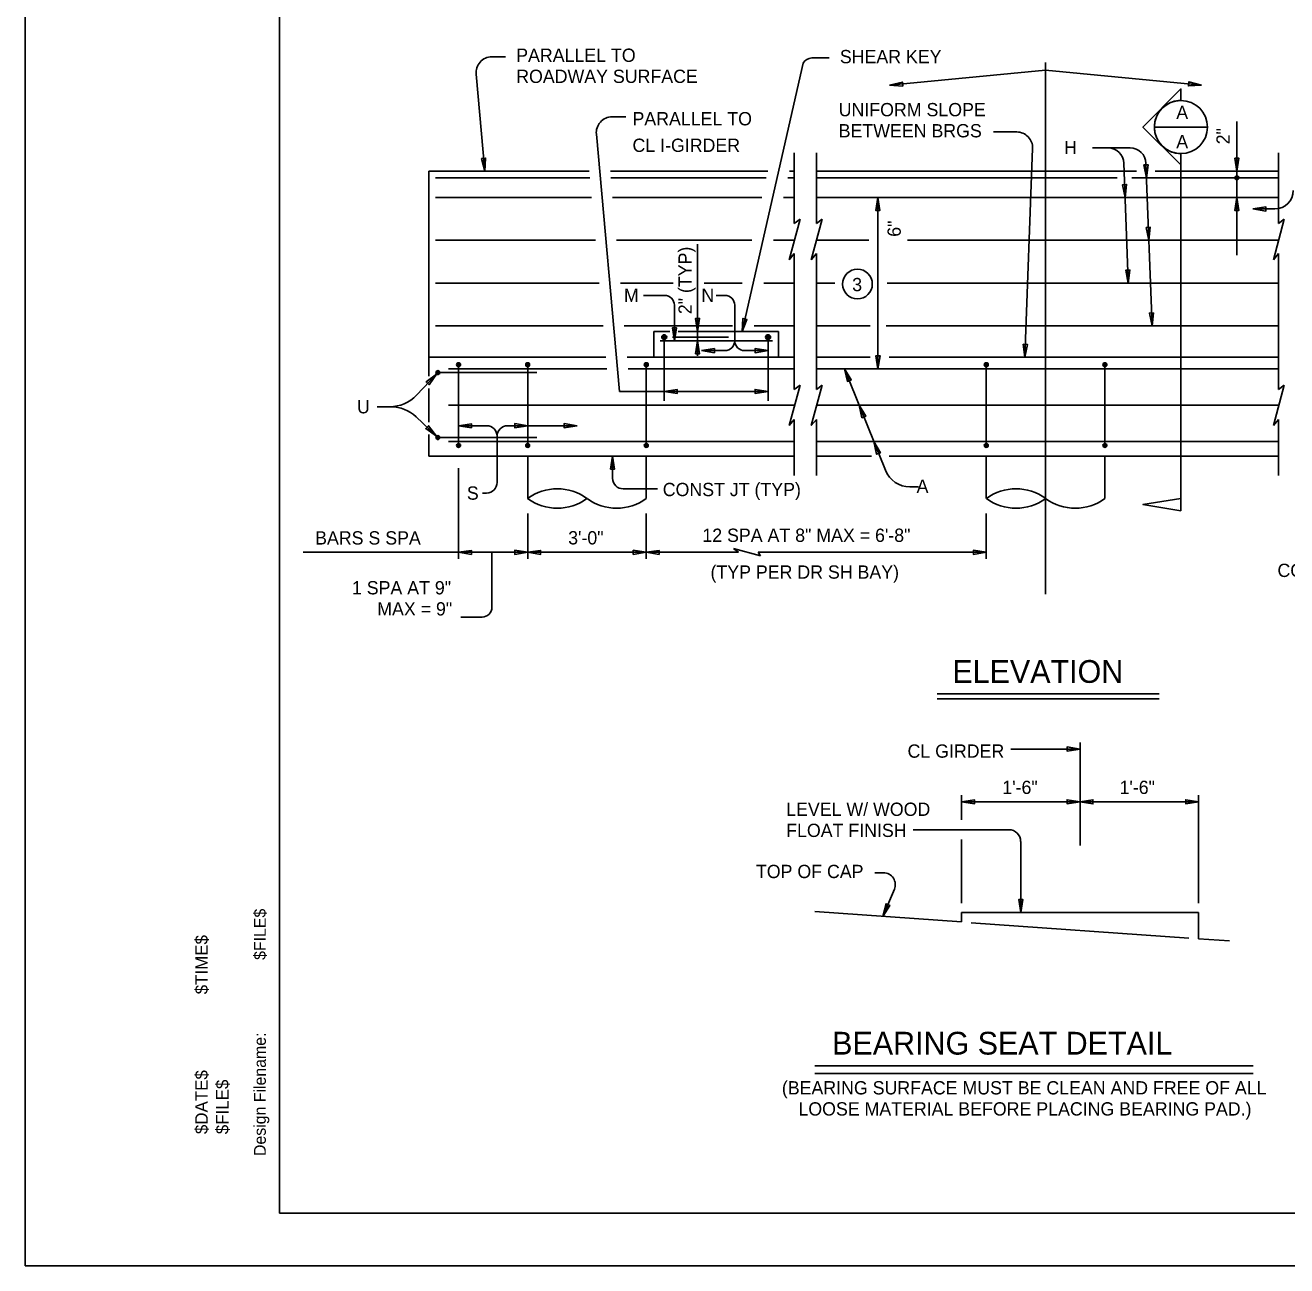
# Model space of a CAD drawing. Extents: x 926 to 1074, y 990 to 1081.
# Drawn here: x 1000 to 1011.97, y 1000 to 1011.77 of the extents above; entities that cross this region are included whole.
import ezdxf

# ---------------------------------------------------------------- set-up
doc = ezdxf.new("R2010")
doc.units = 0
for name, color, linetype in [('BORD_lines_major', 7, 'Continuous'), ('BORD_text_filename_date', 7, 'Continuous'), ('D_BATCH_PLOT', 7, 'Continuous'), ('D_SHEET', 7, 'Continuous'), ('D_SHEET_TXT_SUB_CODE', 7, 'Continuous'), ('Default', 7, 'Continuous'), ('Working Level 1', 7, 'Continuous')]:
    doc.layers.add(name, color=color, linetype=linetype)

msp = doc.modelspace()

# ---------------------------------------------------------------- linework, layer by layer
at = {"layer": 'BORD_lines_major'}
for q in [(1002.413, 1021.382), (1033.5, 1000.5)]:
    msp.add_line((1002.413, 1000.5), q, dxfattribs=at)
at = {"layer": 'D_BATCH_PLOT'}
msp.add_lwpolyline([(1000, 1000), (1034, 1000), (1034, 1022), (1000, 1022)], close=True, dxfattribs=at)
at = {"layer": 'D_SHEET'}
for q in [(1000, 1022), (1034, 1000)]:
    msp.add_line((1000, 1000), q, dxfattribs=at)
at = {"layer": 'Default'}
msp.add_line((1010.71, 1010.801), (1011.214, 1010.801), dxfattribs=at)
for points in [[(1010.962, 1011.053), (1010.94, 1011.052), (1010.919, 1011.049), (1010.897, 1011.045), (1010.876, 1011.038), (1010.856, 1011.03), (1010.836, 1011.019), (1010.818, 1011.008), (1010.8, 1010.994), (1010.784, 1010.979), (1010.769, 1010.963), (1010.756, 1010.946), (1010.744, 1010.927), (1010.734, 1010.908), (1010.726, 1010.887), (1010.719, 1010.866), (1010.714, 1010.845), (1010.711, 1010.823), (1010.71, 1010.801), (1010.711, 1010.779), (1010.714, 1010.757), (1010.719, 1010.736), (1010.726, 1010.715), (1010.734, 1010.695), (1010.744, 1010.675), (1010.756, 1010.657), (1010.769, 1010.639), (1010.784, 1010.623), (1010.8, 1010.608), (1010.818, 1010.595), (1010.836, 1010.583), (1010.856, 1010.573), (1010.876, 1010.564), (1010.897, 1010.558), (1010.919, 1010.553), (1010.94, 1010.55), (1010.962, 1010.549), (1010.962, 1010.441), (1010.602, 1010.801), (1010.962, 1011.162)], [(1010.962, 1007.162), (1010.602, 1007.22), (1010.962, 1007.278)]]:
    msp.add_lwpolyline(points, close=True, dxfattribs=at)
msp.add_lwpolyline([(1010.962, 1010.549), (1010.962, 1007.162)], dxfattribs=at)
msp.add_circle((1010.962, 1010.801), 0.252, dxfattribs=at)
at = {"layer": 'Working Level 1'}
for p, q in [((1004.426, 1011.467), (1004.555, 1011.467)), ((1006.799, 1008.862), (1007.379, 1011.407)), ((1007.627, 1011.456), (1007.461, 1011.456)), ((1009.679, 1006.37), (1009.679, 1011.412)), ((1004.36, 1010.383), (1004.277, 1011.301)), ((1009.679, 1011.339), (1008.199, 1011.198)), ((1009.679, 1011.339), (1011.158, 1011.198)), ((1005.567, 1010.898), (1005.696, 1010.898)), ((1011.493, 1009.585), (1011.493, 1010.852)), ((1005.638, 1008.293), (1005.418, 1010.732)), ((1009.405, 1010.754), (1009.184, 1010.754)), ((1007.294, 1009.887), (1007.294, 1010.555)), ((1007.504, 1009.887), (1007.504, 1010.555)), ((1009.481, 1008.617), (1009.555, 1010.598)), ((1010.125, 1010.603), (1010.481, 1010.603)), ((1011.888, 1009.887), (1011.888, 1010.555)), ((1010.463, 1009.342), (1010.421, 1010.459)), ((1010.688, 1008.915), (1010.63, 1010.459)), ((1003.828, 1010.383), (1003.828, 1008.617)), ((1005.349, 1010.383), (1003.828, 1010.383)), ((1005.354, 1010.32), (1003.891, 1010.32)), ((1007.043, 1010.383), (1005.55, 1010.383)), ((1007.029, 1010.32), (1005.555, 1010.32)), ((1007.294, 1010.32), (1007.234, 1010.32)), ((1007.294, 1010.383), (1007.248, 1010.383)), ((1010.541, 1010.383), (1007.504, 1010.383)), ((1010.358, 1010.32), (1007.504, 1010.32)), ((1011.888, 1010.32), (1010.497, 1010.32)), ((1011.888, 1010.383), (1010.719, 1010.383)), ((1005.371, 1010.133), (1003.891, 1010.133)), ((1006.986, 1010.133), (1005.572, 1010.133)), ((1007.294, 1010.133), (1007.191, 1010.133)), ((1011.888, 1010.133), (1007.504, 1010.133)), ((1008.088, 1008.509), (1008.088, 1010.133)), ((1011.645, 1010.024), (1011.853, 1010.024)), ((1007.246, 1009.542), (1007.35, 1009.926)), ((1007.35, 1009.926), (1007.294, 1009.887)), ((1007.455, 1009.542), (1007.559, 1009.926)), ((1007.559, 1009.926), (1007.504, 1009.887)), ((1011.839, 1009.542), (1011.943, 1009.926)), ((1011.943, 1009.926), (1011.888, 1009.887)), ((1005.408, 1009.727), (1003.891, 1009.727)), ((1006.893, 1009.727), (1005.609, 1009.727)), ((1007.296, 1009.727), (1007.099, 1009.727)), ((1008.003, 1009.727), (1007.505, 1009.727)), ((1008.37, 1009.727), (1011.889, 1009.727)), ((1006.377, 1008.631), (1006.377, 1009.691)), ((1007.294, 1009.601), (1007.246, 1009.542)), ((1007.294, 1008.313), (1007.294, 1009.601)), ((1007.504, 1009.601), (1007.455, 1009.542)), ((1007.504, 1008.313), (1007.504, 1009.601)), ((1011.888, 1009.601), (1011.839, 1009.542)), ((1011.888, 1008.313), (1011.888, 1009.601)), ((1005.445, 1009.321), (1003.891, 1009.321)), ((1006.145, 1009.321), (1005.645, 1009.321)), ((1006.801, 1009.321), (1006.44, 1009.321)), ((1007.294, 1009.321), (1007.006, 1009.321)), ((1007.68, 1009.321), (1007.504, 1009.321)), ((1008.176, 1009.321), (1011.888, 1009.321)), ((1006.064, 1009.203), (1005.865, 1009.203)), ((1006.158, 1008.772), (1006.158, 1009.11)), ((1006.554, 1009.203), (1006.636, 1009.203)), ((1006.73, 1008.774), (1006.73, 1009.11)), ((1005.481, 1008.915), (1003.891, 1008.915)), ((1006.708, 1008.915), (1005.682, 1008.915)), ((1007.294, 1008.915), (1006.914, 1008.915)), ((1008.015, 1008.915), (1007.504, 1008.915)), ((1008.167, 1008.915), (1011.888, 1008.915)), ((1005.961, 1008.862), (1006.115, 1008.862)), ((1005.961, 1008.617), (1005.961, 1008.862)), ((1007.088, 1008.772), (1006.023, 1008.772)), ((1006.061, 1008.205), (1006.061, 1008.808)), ((1006.67, 1008.808), (1006.139, 1008.808)), ((1006.193, 1008.862), (1007.146, 1008.862)), ((1007.046, 1008.205), (1007.046, 1008.808)), ((1007.146, 1008.862), (1007.146, 1008.617)), ((1006.636, 1008.68), (1006.414, 1008.68)), ((1007.046, 1008.68), (1006.824, 1008.68)), ((1003.828, 1008.617), (1003.828, 1008.438)), ((1005.508, 1008.617), (1003.828, 1008.617)), ((1005.518, 1008.509), (1004.016, 1008.509)), ((1004.11, 1008.547), (1004.11, 1007.781)), ((1004.766, 1008.547), (1004.766, 1007.781)), ((1007.294, 1008.617), (1005.709, 1008.617)), ((1007.294, 1008.509), (1005.719, 1008.509)), ((1005.891, 1008.547), (1005.891, 1007.781)), ((1008.015, 1008.617), (1007.504, 1008.617)), ((1011.888, 1008.509), (1007.504, 1008.509)), ((1008.159, 1007.545), (1007.772, 1008.509)), ((1008.194, 1008.617), (1009.679, 1008.617)), ((1009.116, 1008.547), (1009.116, 1007.781)), ((1009.669, 1008.617), (1011.888, 1008.617)), ((1010.241, 1008.547), (1010.241, 1007.781)), ((1003.901, 1008.458), (1003.711, 1008.257)), ((1004.852, 1008.472), (1003.914, 1008.472)), ((1003.828, 1008.321), (1003.828, 1008.001)), ((1007.046, 1008.293), (1005.638, 1008.293)), ((1007.246, 1007.969), (1007.35, 1008.353)), ((1007.35, 1008.353), (1007.294, 1008.313)), ((1007.455, 1007.969), (1007.559, 1008.353)), ((1007.559, 1008.353), (1007.504, 1008.313)), ((1011.839, 1007.969), (1011.943, 1008.353)), ((1011.943, 1008.353), (1011.888, 1008.313)), ((1007.299, 1008.164), (1004.016, 1008.164)), ((1011.892, 1008.164), (1007.508, 1008.164)), ((1003.339, 1008.148), (1003.467, 1008.148)), ((1003.708, 1008.052), (1003.901, 1007.869)), ((1004.11, 1007.968), (1004.379, 1007.968)), ((1004.576, 1007.968), (1005.235, 1007.968)), ((1007.294, 1008.027), (1007.246, 1007.969)), ((1007.294, 1007.495), (1007.294, 1008.027)), ((1007.504, 1008.027), (1007.455, 1007.969)), ((1007.504, 1007.495), (1007.504, 1008.027)), ((1011.888, 1008.027), (1011.839, 1007.969)), ((1011.888, 1007.495), (1011.888, 1008.027)), ((1003.828, 1007.885), (1003.828, 1007.679)), ((1004.852, 1007.856), (1003.914, 1007.856)), ((1007.294, 1007.818), (1004.016, 1007.818)), ((1004.476, 1007.868), (1004.476, 1007.429)), ((1011.888, 1007.818), (1007.504, 1007.818)), ((1007.294, 1007.679), (1003.828, 1007.679)), ((1004.766, 1007.679), (1004.766, 1007.278)), ((1005.572, 1007.679), (1005.572, 1007.469)), ((1005.891, 1007.679), (1005.891, 1007.278)), ((1008.028, 1007.679), (1007.504, 1007.679)), ((1011.888, 1007.679), (1008.194, 1007.679)), ((1009.116, 1007.679), (1009.116, 1007.278)), ((1009.116, 1007.679), (1009.116, 1007.278)), ((1009.116, 1007.679), (1009.116, 1007.278)), ((1009.116, 1007.679), (1009.116, 1007.278)), ((1009.116, 1007.679), (1009.116, 1007.278)), ((1009.116, 1007.679), (1009.116, 1007.278)), ((1010.241, 1007.679), (1010.241, 1007.278)), ((1004.11, 1007.564), (1004.11, 1006.706)), ((1004.376, 1007.329), (1004.338, 1007.329)), ((1005.672, 1007.369), (1005.998, 1007.369)), ((1008.473, 1007.388), (1008.391, 1007.388)), ((1004.766, 1007.136), (1004.766, 1006.706)), ((1005.891, 1007.136), (1005.891, 1006.706)), ((1009.116, 1007.136), (1009.116, 1006.706)), ((1006.765, 1006.767), (1002.635, 1006.767)), ((1004.427, 1006.767), (1004.427, 1006.247)), ((1006.765, 1006.767), (1006.719, 1006.804)), ((1006.719, 1006.804), (1006.975, 1006.735)), ((1006.975, 1006.735), (1006.953, 1006.767)), ((1009.116, 1006.767), (1006.953, 1006.767)), ((1004.333, 1006.153), (1004.133, 1006.153)), ((1008.65, 1005.426), (1010.756, 1005.426)), ((1008.65, 1005.376), (1010.756, 1005.376)), ((1010.005, 1004.963), (1010.005, 1004.838)), ((1010.005, 1004.901), (1009.349, 1004.901)), ((1010.005, 1003.986), (1010.005, 1004.838)), ((1008.88, 1004.23), (1008.88, 1004.463)), ((1011.13, 1003.438), (1011.13, 1004.463)), ((1008.88, 1004.401), (1011.13, 1004.401)), ((1008.423, 1004.136), (1009.33, 1004.136)), ((1008.88, 1003.438), (1008.88, 1004.042)), ((1009.443, 1003.351), (1009.443, 1004.024)), ((1008.06, 1003.728), (1008.141, 1003.728)), ((1008.244, 1003.571), (1008.135, 1003.313)), ((1008.88, 1003.261), (1007.49, 1003.359)), ((1008.88, 1003.351), (1011.13, 1003.351)), ((1008.88, 1003.261), (1008.88, 1003.351)), ((1008.974, 1003.254), (1011.037, 1003.107)), ((1011.13, 1003.351), (1011.13, 1003.102)), ((1011.423, 1003.082), (1011.13, 1003.102)), ((1007.489, 1001.895), (1011.649, 1001.895)), ((1007.489, 1001.825), (1011.649, 1001.825))]:
    msp.add_line(p, q, dxfattribs=at)
for points in [[(1008.199, 1011.198), (1008.323, 1011.19), (1008.32, 1011.228)], [(1011.158, 1011.198), (1011.038, 1011.23), (1011.034, 1011.191)], [(1004.36, 1010.383), (1004.367, 1010.506), (1004.328, 1010.502)], [(1010.636, 1010.32), (1010.611, 1010.442), (1010.65, 1010.443)], [(1011.493, 1010.383), (1011.513, 1010.505), (1011.475, 1010.505)], [(1010.433, 1010.133), (1010.409, 1010.254), (1010.447, 1010.256)], [(1008.088, 1010.133), (1008.068, 1010.01), (1008.107, 1010.01)], [(1011.493, 1010.133), (1011.473, 1010.01), (1011.512, 1010.01)], [(1011.645, 1010.024), (1011.768, 1010.004), (1011.768, 1010.043)], [(1010.658, 1009.727), (1010.633, 1009.848), (1010.672, 1009.85)], [(1010.463, 1009.321), (1010.439, 1009.443), (1010.478, 1009.444)], [(1010.688, 1008.915), (1010.664, 1009.037), (1010.702, 1009.038)], [(1006.158, 1008.772), (1006.178, 1008.895), (1006.139, 1008.895)], [(1006.377, 1008.862), (1006.397, 1008.985), (1006.358, 1008.985)], [(1006.799, 1008.862), (1006.807, 1008.986), (1006.845, 1008.977)], [(1006.377, 1008.772), (1006.397, 1008.65), (1006.358, 1008.65)], [(1006.414, 1008.68), (1006.537, 1008.66), (1006.537, 1008.699)], [(1007.046, 1008.68), (1006.923, 1008.66), (1006.923, 1008.699)], [(1008.088, 1008.509), (1008.108, 1008.632), (1008.069, 1008.632)], [(1009.481, 1008.617), (1009.506, 1008.739), (1009.467, 1008.74)], [(1007.772, 1008.509), (1007.799, 1008.388), (1007.835, 1008.402)], [(1003.901, 1008.458), (1003.803, 1008.383), (1003.831, 1008.356)], [(1006.061, 1008.293), (1006.183, 1008.273), (1006.183, 1008.312)], [(1007.046, 1008.293), (1006.923, 1008.313), (1006.923, 1008.274)], [(1007.91, 1008.164), (1007.937, 1008.043), (1007.973, 1008.057)], [(1003.901, 1007.869), (1003.826, 1007.968), (1003.799, 1007.94)], [(1004.11, 1007.968), (1004.232, 1007.948), (1004.232, 1007.986)], [(1004.766, 1007.968), (1004.643, 1007.988), (1004.643, 1007.949)], [(1005.235, 1007.968), (1005.112, 1007.988), (1005.112, 1007.949)], [(1008.049, 1007.818), (1008.076, 1007.697), (1008.112, 1007.712)], [(1005.572, 1007.679), (1005.552, 1007.557), (1005.59, 1007.557)], [(1004.11, 1006.767), (1004.232, 1006.747), (1004.232, 1006.785)], [(1004.766, 1006.767), (1004.643, 1006.787), (1004.643, 1006.748)], [(1004.766, 1006.767), (1004.888, 1006.747), (1004.888, 1006.785)], [(1005.891, 1006.767), (1005.768, 1006.787), (1005.768, 1006.748)], [(1005.891, 1006.767), (1006.013, 1006.747), (1006.013, 1006.785)], [(1009.116, 1006.767), (1008.994, 1006.787), (1008.994, 1006.748)], [(1010.005, 1004.901), (1009.883, 1004.921), (1009.883, 1004.882)], [(1008.88, 1004.401), (1009.003, 1004.381), (1009.003, 1004.42)], [(1010.005, 1004.401), (1009.883, 1004.421), (1009.883, 1004.382)], [(1010.005, 1004.401), (1010.128, 1004.381), (1010.128, 1004.42)], [(1011.13, 1004.401), (1011.008, 1004.421), (1011.008, 1004.382)], [(1008.135, 1003.313), (1008.201, 1003.418), (1008.166, 1003.433)], [(1009.443, 1003.351), (1009.463, 1003.473), (1009.424, 1003.473)]]:
    msp.add_lwpolyline(points, close=True, dxfattribs=at)
for centre, radius in [((1011.493, 1010.32), 0.0187), ((1011.493, 1010.32), 0.0117), ((1011.493, 1010.32), 0.00469), ((1007.894, 1009.312), 0.141), ((1006.061, 1008.808), 0.0235), ((1006.061, 1008.808), 0.0188), ((1006.061, 1008.808), 0.0141), ((1006.061, 1008.808), 0.0094), ((1006.061, 1008.808), 0.0047), ((1007.046, 1008.808), 0.0235), ((1007.046, 1008.808), 0.0188), ((1007.046, 1008.808), 0.0141), ((1007.046, 1008.808), 0.0094), ((1007.046, 1008.808), 0.0047), ((1004.11, 1008.547), 0.0187), ((1004.11, 1008.547), 0.0117), ((1004.11, 1008.547), 0.00469), ((1004.766, 1008.547), 0.0187), ((1004.766, 1008.547), 0.0117), ((1004.766, 1008.547), 0.00469), ((1005.891, 1008.547), 0.0187), ((1005.891, 1008.547), 0.0117), ((1005.891, 1008.547), 0.00469), ((1009.116, 1008.547), 0.0187), ((1009.116, 1008.547), 0.0117), ((1009.116, 1008.547), 0.00469), ((1010.241, 1008.547), 0.0187), ((1010.241, 1008.547), 0.0117), ((1010.241, 1008.547), 0.00469), ((1003.914, 1008.472), 0.0187), ((1003.914, 1008.472), 0.0117), ((1003.914, 1008.472), 0.00469), ((1003.914, 1007.856), 0.0187), ((1003.914, 1007.856), 0.0117), ((1003.914, 1007.856), 0.00469), ((1004.11, 1007.781), 0.0187), ((1004.11, 1007.781), 0.0117), ((1004.766, 1007.781), 0.0187), ((1004.766, 1007.781), 0.0117), ((1005.891, 1007.781), 0.0187), ((1005.891, 1007.781), 0.0117), ((1009.116, 1007.781), 0.0187), ((1009.116, 1007.781), 0.0117), ((1010.241, 1007.781), 0.0187), ((1010.241, 1007.781), 0.0117), ((1004.11, 1007.781), 0.00469), ((1004.766, 1007.781), 0.00469), ((1005.891, 1007.781), 0.00469), ((1009.116, 1007.781), 0.00469), ((1010.241, 1007.781), 0.00469)]:
    msp.add_circle(centre, radius, dxfattribs=at)
for centre, radius, start, end in [((1004.426, 1011.317), 0.15, 90, 186.147), ((1007.461, 1011.362), 0.0938, 90, 151.3075), ((1005.567, 1010.748), 0.15, 90, 186.147), ((1009.405, 1010.604), 0.15, 357.861, 90), ((1010.271, 1010.453), 0.15, 2.1377, 90), ((1010.481, 1010.453), 0.15, 2.14, 90), ((1011.853, 1010.199), 0.175, 270, 0), ((1006.064, 1009.11), 0.0938, 0, 90), ((1006.636, 1009.11), 0.0938, 360, 90), ((1006.636, 1008.774), 0.0938, 270, 0), ((1006.824, 1008.774), 0.0938, 180, 270), ((1003.457, 1008.498), 0.35, 270, 316.4606), ((1003.467, 1007.798), 0.35, 46.4299, 90), ((1004.376, 1007.868), 0.1, 0, 88.1727), ((1004.576, 1007.868), 0.1, 90, 180), ((1005.672, 1007.469), 0.1, 180, 270), ((1008.391, 1007.638), 0.25, 201.8559, 270), ((1004.376, 1007.429), 0.1, 270, 360), ((1005.047, 1006.896), 0.474, 53.5974, 126.4026), ((1009.398, 1006.896), 0.474, 53.5974, 126.4026), ((1009.398, 1006.896), 0.474, 53.5974, 126.4026), ((1009.398, 1006.896), 0.474, 53.5974, 126.4026), ((1009.398, 1006.896), 0.474, 53.5974, 126.4026), ((1009.398, 1006.896), 0.474, 53.5974, 126.4026), ((1009.398, 1006.896), 0.474, 53.5974, 126.4026), ((1005.047, 1007.659), 0.474, 233.5974, 306.4026), ((1005.61, 1007.659), 0.474, 233.5974, 306.4026), ((1009.398, 1007.659), 0.474, 233.5974, 306.4026), ((1009.398, 1007.659), 0.474, 233.5974, 306.4026), ((1009.398, 1007.659), 0.474, 233.5974, 306.4026), ((1009.398, 1007.659), 0.474, 233.5974, 306.4026), ((1009.398, 1007.659), 0.474, 233.5974, 306.4026), ((1009.398, 1007.659), 0.474, 233.5974, 306.4026), ((1009.96, 1007.659), 0.474, 233.5974, 306.4026), ((1004.333, 1006.247), 0.0938, 270, 0), ((1009.33, 1004.024), 0.112, 0, 90), ((1008.141, 1003.615), 0.112, 337.1387, 90)]:
    msp.add_arc(centre, radius, start, end, dxfattribs=at)

# ---------------------------------------------------------------- texts
at = {"layer": 'BORD_text_filename_date'}
for s, height, p in [('$FILE$', 0.1126, (1002.282, 1002.901)), ('Design Filename:', 0.11256, (1002.282, 1001.041))]:
    msp.add_text(s, height=height, rotation=89.9834, dxfattribs=at).set_placement(p)
at = {"layer": 'D_SHEET_TXT_SUB_CODE'}
for s, p in [('$TIME$', (1001.732, 1002.575)), ('$DATE$', (1001.732, 1001.249)), ('$FILE$', (1001.929, 1001.248))]:
    msp.add_text(s, height=0.12, rotation=90, dxfattribs=at).set_placement(p)
at = {"layer": 'Default'}
for p in [(1010.918, 1010.877), (1010.918, 1010.6)]:
    msp.add_text('A', height=0.126, dxfattribs=at).set_placement(p)
at = {"layer": 'Working Level 1'}
for s, height, p in [('PARALLEL TO', 0.126, (1004.657, 1011.419)), ('SHEAR KEY', 0.126, (1007.727, 1011.406)), ('ROADWAY SURFACE', 0.126, (1004.657, 1011.219)), ('UNIFORM SLOPE', 0.126, (1007.716, 1010.903)), ('PARALLEL TO', 0.126, (1005.76, 1010.817)), ('BETWEEN BRGS', 0.126, (1007.716, 1010.703)), ('CL I-GIRDER', 0.126, (1005.76, 1010.565)), (' H', 0.126, (1009.807, 1010.544)), ('3', 0.126, (1007.844, 1009.244)), ('M', 0.126, (1005.679, 1009.143)), ('N', 0.126, (1006.413, 1009.143)), ('U ', 0.126, (1003.147, 1008.085)), ('CONST JT (TYP)', 0.126, (1006.047, 1007.3)), (' A ', 0.126, (1008.408, 1007.331)), ('S ', 0.126, (1004.189, 1007.266)), ('BARS S SPA', 0.126, (1002.75, 1006.841)), ('3\'-0"', 0.126, (1005.15, 1006.842)), ('12 SPA AT 8" MAX = 6\'-8"', 0.126, (1006.423, 1006.866)), ('(TYP PER DR SH BAY)', 0.126, (1006.5, 1006.517)), ('CONST JT (TYP)', 0.126, (1011.878, 1006.533)), ('1 SPA AT 9"', 0.126, (1003.099, 1006.368)), ('MAX = 9"', 0.126, (1003.339, 1006.168)), ('ELEVATION', 0.216, (1008.794, 1005.529)), ('CL GIRDER', 0.126, (1008.369, 1004.819)), ('1\'-6"', 0.126, (1009.268, 1004.475)), ('1\'-6"', 0.126, (1010.38, 1004.475)), ('LEVEL W/ WOOD', 0.126, (1007.218, 1004.267)), ('FLOAT FINISH', 0.126, (1007.218, 1004.067)), ('TOP OF CAP', 0.126, (1006.931, 1003.677)), ('BEARING SEAT DETAIL', 0.216, (1007.654, 1002.003)), ('(BEARING SURFACE MUST BE CLEAN AND FREE OF ALL', 0.126, (1007.177, 1001.625)), ('LOOSE MATERIAL BEFORE PLACING BEARING PAD.)', 0.126, (1007.334, 1001.425))]:
    msp.add_text(s, height=height, dxfattribs=at).set_placement(p)
for s, p in [('2"', (1011.425, 1010.637)), ('6"', (1008.305, 1009.76)), ('2" (TYP)', (1006.322, 1009.026))]:
    msp.add_text(s, height=0.126, rotation=90, dxfattribs=at).set_placement(p)

doc.saveas('drawing.dxf')
